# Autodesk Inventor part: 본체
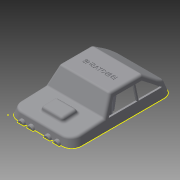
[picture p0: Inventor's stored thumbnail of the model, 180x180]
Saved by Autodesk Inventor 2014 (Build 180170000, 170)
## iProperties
Created: 2015-05
Part Number: 본체
Material: 일반
Document SubType Name: Modeling
Designer: Administrator
Density: 1 g/cm^3
Appearance: 기본값
Author: Administrator
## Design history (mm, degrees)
sketch "스케치1"
  geometry: L1 (0, 0)-(122, 0); L2 (122, 0)-(122, 10); L3 (92, 30)-(53.691, 30); L4 (0, 30)-(0, 0); L5 (122, 0)-(119.321, 10); L6 (122, 0)-(142.851, 0); L7 (122, 30)-(122, 10); L8 (122, 10)-(92, 10); L9 (92, 10)-(92, 30); L10 (119.321, 10)-(92, 30); L11 (0, 0)-(2.679, 10); L12 (0, 0)-(10.353, 0); L13 (0, 0)-(0, 9); L14 (2.446, 9.128)-(13.282, 11.02); L15 (13.282, 11.02)-(18.714, 11.02); L16 (13.282, 11.02)-(33.255, 12.067); L17 (2.446, 9.128)-(41.942, 11.198); L18 (0, 9)-(42, 9); L19 (41.942, 11.198)-(53.691, 30)
  constraints: 38 end point, 5 horizontal, 4 perpendicular, 4 point on line, 2 parallel, 1 equal length
  dimensions: "d0" = 122 distance of L1.start L1.end; "d1" = 30 distance of L1.end L7.start; "d2" = 105 deg angle of L6 L5; "d3" = 20 distance of L2.end L7.start; "d4" = 30 distance of L2.end L8.end; "d5" = 75 deg angle of L12 L11; "d6" = 9 distance of L1.start L13.end; "d8" = 11 distance of L14.start L14.end; "d11" = 20 distance of L14.end L16.end; "d13" = 42 distance of L13.end L17.end; "d14" = 3 deg angle of L18 L17; "d15" = 125 deg angle of L19 L17
extrude "돌출1" new body sketch "스케치1" distance "d16" = 76; taper "d17" = 0 deg
node "작업 평면1"
sketch "스케치2"
  geometry: L1 (-10, 119.321)-(-30, 92) reference; L2 (0, 122)-(-10, 119.321) reference; L3 (0, 0)-(0, 122) reference; L4 (-9.128, 2.446)-(0, 0) reference; L5 (-11.198, 41.942)-(-9.128, 2.446) reference; L6 (-30, 53.691)-(-11.198, 41.942) reference; L7 (-30, 92)-(-30, 53.691) reference; L8 (-9.128, 2.446)-(-9.704, 13.431); L9 (-9.704, 13.431)-(-14.697, 13.169); L10 (-14.697, 13.169)-(-15.744, 33.142); L11 (-15.744, 33.142)-(-10.751, 33.403); L12 (-9.704, 13.431)-(-4.383, 13.431); L13 (-9.704, 13.431)-(-14.792, 14.986); L14 (-9.704, 13.431)-(-4.383, 13.431); L15 (-10.751, 33.403)-(-15.679, 31.897); L16 (-10.751, 33.403)-(-5.598, 33.403); 1 further point
  constraints: 18 end point, 4 point on line, 3 horizontal, 3 perpendicular, 2 equal length
  dimensions: "d18" = 11 distance of L4.start L8.end; "d19" = 5 distance of L8.end L9.end; "d22" = 20 distance of L9.end L10.end; "d24" = 163 deg angle of L14 L13; "d25" = 163 deg angle of L15 L16
extrude "돌출2" join sketch "스케치2" stored distance "d26" = 26; taper "d27" = 0 deg
sketch "스케치3"
  geometry: L1 (0, 0)-(0, 10) reference; L2 (0, 10)-(-76, 10) reference; L3 (-76, 0)-(-76, 10) reference; L4 (0, 0)-(-76, 0) reference; L5 (0, 10)-(0, 30) reference; L6 (0, 30)-(-76, 30) reference; L7 (-76, 10)-(-76, 30) reference; L8 (0, 10)-(-76, 10) reference; L9 (0, 0)-(-8.038, 30); L10 (0, 0)-(31.058, 0); L11 (-8.038, 30)-(0, 30); L12 (0, 30)-(0, 0); L13 (-76, 0)-(-67.962, 30); L14 (-76, 0)-(-44.942, 0); L15 (-67.962, 30)-(-76, 30); L16 (-76, 30)-(-76, 0); 1 further point
  constraints: 16 end point, 4 collinear, 2 equal length, 2 horizontal, 2 point on line
  dimensions: "d28" = 105 deg angle of L10 L9; "d29" = 75 deg angle of L14 L13
extrude "돌출3" cut sketch "스케치3" distance "d30" = 122; taper "d31" = 0 deg
sketch "스케치7"
  geometry: 1 further point
node "작업 평면4"
sketch "스케치8"
  geometry: L1 (76, 0)-(0, 0) reference; L2 (38, 0)-(38, -21); L3 (38, -21)-(38, -61); L4 (38, -61)-(38, -101); L5 (38, -61)-(60, -61); L6 (38, -61)-(16, -61); C1 r 3 at (38, -101); C2 r 3 at (16, -61); C3 r 3 at (38, -21); C4 r 3 at (60, -61); 1 further point
  constraints: 10 end point, 4 centre point, 4 coincident, 3 collinear, 2 perpendicular, 1 midpoint
  dimensions: "d47" = 21 distance of L2.start L2.end; "d48" = 40 distance of L2.end L3.end; "d49" = 40 distance of L3.end L4.end; "d51" = 22 distance of L3.end L5.end; "d52" = 22 distance of L3.end L6.end; "d53" = 6 diameter of C1; "d54" = 6 diameter of C2; "d55" = 6 diameter of C3; "d56" = 6 diameter of C4
extrude "돌출6" join sketch "스케치8" stored distance "d57" = 10; taper "d58" = 0 deg
sketch "스케치9"
  geometry: L1 (0, 119.929)-(0, 2.071) reference; L2 (1, 24)-(1, 18) reference; L3 (1, 24)-(1, 18) reference; L4 (1, 104)-(1, 98) reference; L5 (1, 24)-(-2, 24); L6 (0, 18)-(13.466, 18); L7 (-2, 24)-(-2, 18); L8 (-2, 21)-(-2, 26); L9 (-2, 26)-(-13.808, 28.082); L10 (-2, 21)-(3, 21); L11 (-2, 21)-(-2, 16); L12 (-2, 16)-(-10.835, 14.442); L13 (-10.835, 14.442)-(-13.493, 15.791); L14 (-13.493, 15.791)-(-13.808, 28.082); 5 further points
  constraints: 20 end point, 3 perpendicular, 2 horizontal, 1 collinear, 1 midpoint, 1 point on line
  dimensions: "d59" = 3 distance of L3.start L5.end; "d62" = 5 distance of L8.start L8.end; "d63" = 100 deg angle of L9 L8; "d66" = 5 distance of L8.start L11.end; "d67" = 100 deg angle of L11 L12
extrude "돌출7" join sketch "스케치9" stored distance "d68" = 2; taper "d69" = 0 deg
sketch "스케치10"
  geometry: C1 r 3 at (0, 0) reference; C2 r 3 at (-44, 0) reference; C3 r 3 at (-22, 40) reference; C4 r 3 at (-22, -40) reference; C5 r 3 at (0, 0) reference; 1 further point
extrude "돌출8" cut sketch "스케치10" distance "d70" = 1; taper "d71" = 0 deg
sketch "스케치11"
  geometry: L1 (-2.446, 9.128)-(0, 0) reference; L2 (-76, 0)-(-73.554, 9.128) reference; L3 (-2.446, 9.128)-(-73.554, 9.128) reference; L4 (-38, 0)-(-28, 0); L5 (-28, 0)-(-17, 0); L6 (-38, 0)-(-48, 0); L7 (-48, 0)-(-59, 0); L8 (-17, 0)-(-12.24, 0); L9 (-59, 0)-(-64.879, 0); A1 r 4 centre (-17, 0) between (-13, 0) and (-21, 0); A2 r 4 centre (-28, 0) between (-24, 0) and (-32, 0); A3 r 4 centre (-48, 0) between (-44, 0) and (-52, 0); A4 r 4 centre (-59, 0) between (-55, 0) and (-63, 0); 1 further point
  constraints: 12 end point, 8 point on circle, 8 point on line, 4 centre point, 4 coincident, 8 other
  dimensions: "d72" = 10 distance of L4.start L4.end; "d73" = 11 distance of L4.end L5.end; "d74" = 10 distance of L4.start L6.end; "d75" = 11 distance of L6.end L7.end; "d76" = 8 diameter of A1; "d77" = 8 diameter of A2; "d78" = 8 diameter of A3; "d79" = 8 diameter of A4
extrude "돌출9" join sketch "스케치11" stored distance "d80" = 4; taper "d81" = 0 deg
sketch "스케치12"
  geometry: L1 (0, 104)-(0, 98) reference; L2 (-18.737, 104)-(-23.129, 98) reference; L3 (0, 101)-(-2, 101); L4 (-2, 101)-(-2, 106); L5 (-2, 106)-(-17.244, 108.688); L6 (-2, 101)-(-2, 96); L7 (-2, 96)-(-28.98, 91.243); L8 (-28.98, 91.243)-(-17.244, 108.688); 1 further point
  constraints: 12 end point, 2 perpendicular, 1 collinear, 1 midpoint
  dimensions: "d82" = 2 distance of L3.start L3.end; "d83" = 5 distance of L3.end L4.end; "d84" = 100 deg angle of L5 L4; "d85" = 5 distance of L3.end L6.end; "d86" = 100 deg angle of L6 L7
extrude "돌출10" join sketch "스케치12" stored distance "d87" = 2; taper "d88" = 0 deg
node "작업 평면2"
sketch "스케치13"
  geometry: L1 (0, 64)-(0, 58) reference; L2 (-28, 64)-(-28, 58) reference; L3 (0, 61)-(-2, 61); L4 (-2, 61)-(-2, 66); L5 (-2, 66)-(-28.99, 70.759); L6 (-2, 61)-(-2, 56); L7 (-2, 56)-(-24.732, 51.992); L8 (-24.732, 51.992)-(-28.99, 54.375); L9 (-28.99, 54.375)-(-28.99, 70.759); 1 further point
  constraints: 14 end point, 2 perpendicular, 1 collinear, 1 midpoint, 1 parallel
  dimensions: "d90" = 2 distance of L3.start L3.end; "d91" = 5 distance of L3.end L4.end; "d92" = 100 deg angle of L5 L4; "d93" = 5 distance of L3.end L6.end; "d94" = 100 deg angle of L6 L7
extrude "돌출11" join sketch "스케치13" stored distance "d95" = 2; taper "d96" = 0 deg
node "작업 평면3"
sketch "스케치14"
  geometry: L1 (0, 64)-(0, 58) reference; L2 (-28, 64)-(-28, 58) reference; L3 (0, 61)-(-2, 61); L4 (-2, 61)-(-2, 66); L5 (-2, 66)-(-28.477, 70.669); L6 (-2, 61)-(-2, 56); L7 (-2, 56)-(-26.137, 51.744); L8 (-26.137, 51.744)-(-28.945, 54.893); L9 (-28.945, 54.893)-(-28.477, 70.669); 1 further point
  constraints: 14 end point, 2 perpendicular, 1 collinear, 1 midpoint
  dimensions: "d98" = 2 distance of L3.start L3.end; "d99" = 5 distance of L3.end L4.end; "d100" = 100 deg angle of L5 L4; "d101" = 5 distance of L3.end L6.end; "d102" = 100 deg angle of L6 L7
fillet "모깎기1" dims "d105" = 12
fillet "모깎기2" dims "d106" = 3
sketch "스케치15"
  geometry: L1 (44, 11.591)-(44, 110.409) reference; L2 (32.409, 122)-(-20.409, 122) reference; L3 (-32, 11.591)-(-32, 110.409) reference; L4 (-19, 0)-(-20.409, 0) reference; L5 (-19, -2)-(-19, 0) reference; L6 (-11, -2)-(-19, -2) reference; L7 (-11, -2)-(-11, 0) reference; L8 (-8, 0)-(-11, 0) reference; L9 (-8, -2)-(-8, 0) reference; L10 (0, -2)-(-8, -2) reference; L11 (0, -2)-(0, 0) reference; L12 (12, 0)-(0, 0) reference; L13 (12, -2)-(12, 0) reference; L14 (20, -2)-(12, -2) reference; L15 (20, -2)-(20, 0) reference; L16 (23, 0)-(20, 0) reference; L17 (23, -2)-(23, 0) reference; L18 (31, -2)-(23, -2) reference; L19 (31, -2)-(31, 0) reference; L20 (32.409, 0)-(31, 0) reference; 5 further points; 4 other entities
  constraints: 4 other
feature "쉘2" dims "d107" = 2
sketch "스케치6"
  geometry: L1 (0, 11.591)-(0, 110.409) reference; L2 (-28, 54.8)-(-9.255, 43.087) reference; L3 (-9.255, 43.087)-(-7.207, 4.002) reference; L4 (-7.207, 4.002)-(0, 2.071) reference; L5 (0, 119.929)-(0, 2.071) reference; L6 (0, 119.929)-(-8.802, 117.571) reference; L7 (-8.802, 117.571)-(-28, 91.346) reference; L8 (-28, 91.346)-(-28, 54.8) reference; L9 (-20.599, 47.817)-(-17.646, 51.851); L10 (-25, 56.463)-(-6.055, 44.624); L11 (-25, 90.702)-(-25, 56.463); L12 (-25, 56.463)-(-10, 56.463); L13 (-10, 56.463)-(-10, 47.09); L14 (-10, 47.09)-(-10, 81.09); L15 (-10, 81.09)-(-25, 81.09); L16 (-6.799, 115.229)-(-25.192, 90.103); L17 (-25, 90.365)-(-10, 90.365); L18 (-10, 90.365)-(-10, 110.856); L19 (-10, 110.856)-(-10, 82.856); L20 (-10, 82.856)-(-25, 82.856); L21 (-9.06, 43.659)-(-7.485, 13.597) reference; L22 (-27.776, 55.354)-(-9.06, 43.659) reference; L23 (-27.776, 91.019)-(-27.776, 55.354) reference; L24 (-16.897, 105.881)-(-27.776, 91.019) reference; L25 (0, 110.409)-(-16.897, 105.881) reference; L26 (-7.485, 13.597)-(0, 11.591) reference; 1 further point
  constraints: 24 end point, 7 point on line, 5 perpendicular, 2 parallel, 1 collinear
  dimensions: "d37" = 5 distance of L9.start L9.end; "d40" = 15 distance of L10.start L12.end; "d41" = 34 distance of L13.end L14.end; "d43" = 15 distance of L17.start L17.end; "d44" = 28 distance of L18.end L19.end
extrude "돌출13" cut sketch "스케치6" stored distance "d108" = 80; taper "d109" = 0 deg
fillet "모깎기3" dims "d110" = 3
fillet "모깎기4" dims "d111" = 3
fillet "모깎기5" dims "d112" = 3
chamfer "모따기1" distance "d113" = 1; stored, may be unused: second distance "d114" = 2, angle "d115" = 45 deg
fillet "모깎기6" dims "d116" = 3
extrude "돌출14" join sketch "스케치8" stored distance "d117" = 80; taper "d118" = 0 deg
extrude "돌출15" cut sketch "스케치8" distance "d119" = 1; taper "d120" = 0 deg
extrude "돌출16" join sketch "스케치13" stored distance "d121" = 2; taper "d122" = 0 deg
extrude "돌출17" join sketch "스케치14" stored distance "d123" = 2; taper "d124" = 0 deg
sketch "스케치16"
  geometry: L1 (-1.936, 16.189)-(-1.936, 26.189); L2 (-1.936, 26.189)-(-14.065, 28.328); L3 (-14.065, 28.328)-(-13.521, 16.189); L4 (-1.936, 16.189)-(-10.21, 14.73); L5 (-1.936, 16.189)-(6.466, 16.189); L6 (-10.21, 14.73)-(-13.521, 16.189); L7 (-1.936, 96.344)-(-1.936, 106.344); L8 (-1.936, 106.344)-(-16.514, 108.915); L9 (-1.936, 96.344)-(-29.521, 91.48); L10 (-1.936, 96.344)-(26.075, 96.344); L11 (-29.521, 91.48)-(-16.514, 108.915); 1 further point
  constraints: 22 end point, 2 equal length, 2 horizontal, 1 perpendicular, 1 vertical
  dimensions: "d125" = 10 distance of L1.start L1.end; "d126" = 100 deg angle of L2 L1; "d127" = 170 deg angle of L4 L5; "d128" = 10 distance of L7.start L7.end; "d129" = 100 deg angle of L8 L7; "d130" = 170 deg angle of L9 L10
extrude "돌출18" join sketch "스케치16" stored distance "d131" = 2; taper "d132" = 0 deg
sketch "스케치17"
  geometry: L1 (55.319, 37.437)-(0, 37.437) reference; L2 (58.234, 52.299)-(55.319, 37.437) reference; L3 (3.657, 63.114)-(51.662, 63.114) reference; L4 (0, 37.437)-(-2.915, 52.299) reference; L5 (1.251, 66.646)-(54.068, 66.646) reference; L6 (27.66, 66.646)-(27.66, 16.646); 4 further points; 2 other entities
  constraints: 2 end point, 1 coincident, 1 midpoint, 1 perpendicular, 3 other
  dimensions: "d133" = 50 distance of L6.start L6.end
feature "엠보싱1" sketch "스케치17" dims "d0" = 122, "d1" = 30, "d2" = 105 deg, "d3" = 20, "d4" = 30, "d5" = 75 deg, "d6" = 9, "d8" = 11, "d11" = 20, "d13" = 42, "d14" = 3 deg, "d15" = 125 deg, "d134" = 0.5, "d135" = 0
sketch "스케치18"
  geometry: L1 (-17, 2.071)-(-20.27, 2.071) reference; L2 (-29.929, 11.73)-(-29.929, 110.27) reference; L3 (-20.27, 119.929)-(32.27, 119.929) reference; L4 (41.929, 110.27)-(41.929, 11.73) reference; L5 (32.27, 2.071)-(29, 2.071) reference; L6 (29, 2.071)-(29, 0) reference; L7 (29, 0)-(25, 0) reference; L8 (25, 0)-(25, 2.071) reference; L9 (25, 2.071)-(18, 2.071) reference; L10 (18, 2.071)-(18, 0) reference; L11 (18, 0)-(14, 0) reference; L12 (14, 0)-(14, 2.071) reference; L13 (14, 2.071)-(-2, 2.071) reference; L14 (-2, 2.071)-(-2, 0) reference; L15 (-2, 0)-(-6, 0) reference; L16 (-6, 0)-(-6, 2.071) reference; L17 (-6, 2.071)-(-13, 2.071) reference; L18 (-13, 2.071)-(-13, 0) reference; L19 (-13, 0)-(-17, 0) reference; L20 (-17, 0)-(-17, 2.071) reference; L21 (0, -1)-(-1, -2) reference; L22 (0, -1)-(0, 0) reference; L23 (12, 0)-(0, 0) reference; L24 (12, -1)-(12, 0) reference; L25 (13, -2)-(12, -1) reference; L26 (19, -2)-(13, -2) reference; L27 (20, -1)-(19, -2) reference; L28 (20, -1)-(20, 0) reference; L29 (23, 0)-(20, 0) reference; L30 (23, -1)-(23, 0) reference; L31 (24, -2)-(23, -1) reference; L32 (30, -2)-(24, -2) reference; L33 (31, -1)-(30, -2) reference; L34 (31, -1)-(31, 0) reference; L35 (32.409, 0)-(31, 0) reference; L36 (44, 11.591)-(44, 110.409) reference; L37 (32.409, 122)-(-20.409, 122) reference; L38 (-32, 11.591)-(-32, 110.409) reference; L39 (-19, 0)-(-20.409, 0) reference; L40 (-19, -1)-(-19, 0) reference; L41 (-18, -2)-(-19, -1) reference; L42 (-12, -2)-(-18, -2) reference; L43 (-11, -1)-(-12, -2) reference; L44 (-11, -1)-(-11, 0) reference; L45 (-8, 0)-(-11, 0) reference; L46 (-8, -1)-(-8, 0) reference; L47 (-7, -2)-(-8, -1) reference; L48 (-1, -2)-(-7, -2) reference; L49 (-17, 2.071)-(-20.27, 2.071) reference; L50 (-29.929, 11.73)-(-29.929, 110.27) reference; L51 (-20.27, 119.929)-(32.27, 119.929) reference; L52 (41.929, 110.27)-(41.929, 11.73) reference; L53 (32.27, 2.071)-(29, 2.071) reference; L54 (29, 2.071)-(29, 0) reference; L55 (29, 0)-(25, 0) reference; L56 (25, 0)-(25, 2.071) reference; L57 (25, 2.071)-(18, 2.071) reference; L58 (18, 2.071)-(18, 0) reference; L59 (18, 0)-(14, 0) reference; L60 (14, 0)-(14, 2.071) reference; L61 (14, 2.071)-(-2, 2.071) reference; L62 (-2, 2.071)-(-2, 0) reference; L63 (-2, 0)-(-6, 0) reference; L64 (-6, 0)-(-6, 2.071) reference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; 13 further points; 12 other entities
  constraints: 40 end point, 7 parallel, 40 other
  dimensions: "d136" = 1 distance between parallel lines of L51 L69
extrude "돌출19" join sketch "스케치18" distance "d137" = 1; taper "d138" = 0 deg
sketch "스케치19"
  geometry: C1 r 3 at (0, 0) reference; C2 r 3 at (22, 40) reference; C3 r 3 at (44, 0) reference; C4 r 3 at (22, -40) reference; 6 further points
  constraints: 4 coincident
hole "구멍1" sketch "스케치19" at (22, 40), (44, 0), (0, 0), (22, -40) diameter "d139" = 3.242; stored, may be unused: countersink angle "d143" = 90 deg, drill point angle "d145" = 118 deg; dims "d140" = 9, "d141" = 4, "d142" = 2, "d144" = 11
node "솔리드1"
node "투영된 루프1"
node "투영된 루프2"
node "투영된 루프3"
node "투영된 루프5"
node "투영된 루프9"
node "투영된 루프10"
node "투영된 루프11"
node "투영된 루프12"
node "투영된 루프13"
node "투영된 루프17"
node "투영된 루프18"
node "투영된 루프19"
node "투영된 루프20"
node "투영된 루프21"
other parameters: "d89" = 22, "d97" = -22
